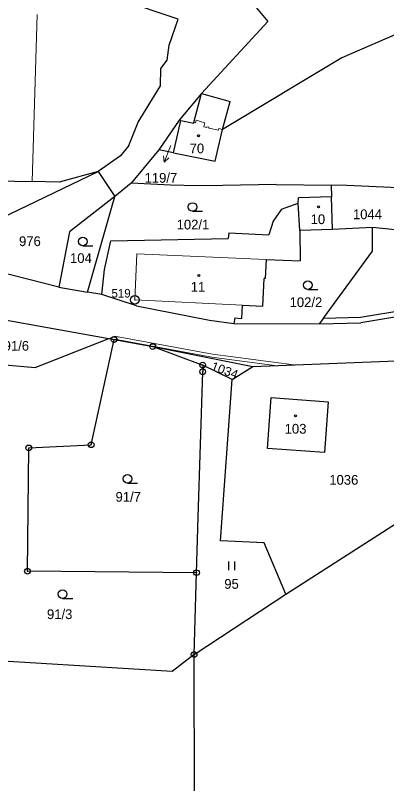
# Model space of a CAD drawing. Extents: x -754970 to -752637, y -970569 to -968179.
# Drawn here: x -752973.4 to -752908.8, y -969522.6 to -969388.8 of the extents above; entities that cross this region are included whole.
import ezdxf
from ezdxf.enums import TextEntityAlignment as Align

# ---------------------------------------------------------------- set-up
doc = ezdxf.new("R2010")
doc.units = 0
doc.header["$LTSCALE"] = 0.68
for name, color, linetype, lineweight in [('1', 7, 'Continuous', 25), ('13', 7, 'Continuous', 13), ('3', 7, 'Continuous', 25), ('4', 7, 'Continuous', 13), ('5', 7, 'Continuous', 25), ('7', 7, 'Continuous', 13), ('8', 7, 'Continuous', 25)]:
    doc.layers.add(name, color=color, linetype=linetype, lineweight=lineweight)
doc.layers.add('2', color=7, linetype='Continuous')

msp = doc.modelspace()

# ---------------------------------------------------------------- linework, layer by layer
at = {"layer": '1'}
for p, q in [((-752945.09, -969389.41), (-752955.13, -969385.98)), ((-752932.64, -969385.92), (-752929.45, -969389.84)), ((-752897.67, -969387.98), (-752916.6, -969396.15)), ((-752946.63, -969393.96), (-752945.09, -969389.41)), ((-752929.45, -969389.84), (-752941, -969402.41)), ((-752946.99, -969396.6), (-752946.63, -969393.96)), ((-752916.6, -969396.15), (-752937.36, -969408.65)), ((-752948.11, -969398.03), (-752946.99, -969396.6)), ((-752948.16, -969401.07), (-752948.11, -969398.03)), ((-752952.03, -969407.36), (-752948.16, -969401.07)), ((-752941, -969402.41), (-752944.89, -969407.01)), ((-752942.33, -969407.44), (-752941, -969402.41)), ((-752941, -969402.41), (-752936.03, -969403.78)), ((-752937.36, -969408.65), (-752936.03, -969403.78)), ((-752944.89, -969407.01), (-752948.44, -969412.22)), ((-752945.87, -969412.71), (-752944.59, -969407.08)), ((-752944.59, -969407.08), (-752942.34, -969407.53)), ((-752953.66, -969411.44), (-752952.03, -969407.36)), ((-752942.34, -969407.53), (-752942.33, -969407.44)), ((-752938.63, -969414.19), (-752937.36, -969408.65)), ((-752953.66, -969411.44), (-752955.11, -969413.24)), ((-752948.44, -969412.22), (-752953.24, -969418)), ((-752945.87, -969412.71), (-752948.44, -969412.22)), ((-752955.11, -969413.24), (-752959, -969415.96)), ((-752945.87, -969412.71), (-752938.63, -969414.19)), ((-752975.99, -969424.16), (-752959, -969415.96)), ((-752959, -969415.96), (-752965.77, -969417.81)), ((-752959, -969415.96), (-752956.07, -969420.31)), ((-752980.48, -969417.53), (-752970.51, -969417.7)), ((-752965.77, -969417.81), (-752970.51, -969417.7)), ((-752953.24, -969418), (-752956.07, -969420.31)), ((-752946.39, -969418.37), (-752953.24, -969418)), ((-752941.73, -969418.49), (-752946.39, -969418.37)), ((-752937.29, -969418.44), (-752941.73, -969418.49)), ((-752928, -969418.24), (-752937.29, -969418.44)), ((-752928, -969418.24), (-752918.45, -969418.33)), ((-752915.73, -969418.39), (-752918.45, -969418.33)), ((-752918.45, -969418.33), (-752918.38, -969420.4)), ((-752906.77, -969418.85), (-752915.73, -969418.39)), ((-752956.07, -969420.31), (-752964.01, -969426.49)), ((-752960.85, -969436.99), (-752956.07, -969420.31)), ((-752918.38, -969420.4), (-752924.13, -969420.58)), ((-752918.18, -969426.06), (-752918.38, -969420.4)), ((-752927.05, -969422.52), (-752924.18, -969421.51)), ((-752924.18, -969421.51), (-752924.13, -969420.58)), ((-752923.9, -969426.28), (-752924.18, -969421.51)), ((-752927.05, -969422.52), (-752928.5, -969424.64)), ((-752928.5, -969424.64), (-752929.26, -969427.01)), ((-752911.21, -969425.74), (-752918.18, -969426.06)), ((-752911.24, -969429.86), (-752911.21, -969425.74)), ((-752907.26, -969426.14), (-752911.21, -969425.74)), ((-752964.01, -969426.49), (-752965.87, -969436.11)), ((-752936.25, -969426.69), (-752936.34, -969427.66)), ((-752936.25, -969426.69), (-752929.26, -969427.01)), ((-752918.18, -969426.06), (-752923.9, -969426.28)), ((-752923.9, -969426.28), (-752923.82, -969431.55)), ((-752957.89, -969433.05), (-752956.78, -969428.07)), ((-752956.78, -969428.07), (-752936.34, -969427.66)), ((-752919.78, -969441.51), (-752911.24, -969429.86)), ((-752929.76, -969431.29), (-752929.93, -969434.61)), ((-752929.76, -969431.29), (-752923.82, -969431.55)), ((-752965.87, -969436.11), (-752979.9, -969432.57)), ((-752958.35, -969437.39), (-752957.89, -969433.05)), ((-752930.3, -969439.43), (-752930.1, -969434.6)), ((-752929.93, -969434.61), (-752930.1, -969434.6)), ((-752965.87, -969436.11), (-752960.85, -969436.99)), ((-752958.35, -969437.39), (-752960.85, -969436.99)), ((-752952.32, -969439.41), (-752958.35, -969437.39)), ((-752913.32, -969441.36), (-752892.34, -969437.83)), ((-752892.24, -969438.82), (-752913.29, -969442.36)), ((-752952.32, -969439.41), (-752939.63, -969441.9)), ((-752933.97, -969441.6), (-752933.85, -969439.26)), ((-752933.85, -969439.26), (-752930.3, -969439.43)), ((-752979.72, -969441.05), (-752957.16, -969445.1)), ((-752935.19, -969441.5), (-752935.36, -969442.49)), ((-752935.19, -969441.5), (-752933.97, -969441.6)), ((-752919.78, -969441.51), (-752920.52, -969442.52)), ((-752919.78, -969441.51), (-752913.32, -969441.36)), ((-752939.63, -969441.9), (-752935.36, -969442.49)), ((-752935.36, -969442.49), (-752920.52, -969442.52)), ((-752920.52, -969442.52), (-752913.29, -969442.36)), ((-752969.96, -969450.14), (-752957.16, -969445.1)), ((-752960.22, -969463.59), (-752956.23, -969445.27)), ((-752949.49, -969446.48), (-752932.04, -969449.98)), ((-752980.96, -969449.2), (-752969.96, -969450.14)), ((-752940.8, -969449.7), (-752940.8, -969450.86)), ((-752935.66, -969452.23), (-752940.8, -969449.7)), ((-752932.04, -969449.98), (-752903.95, -969448.82)), ((-752941.6, -969476.23), (-752940.8, -969450.86)), ((-752935.66, -969452.23), (-752932.04, -969449.98)), ((-752937.68, -969480.36), (-752935.66, -969452.23)), ((-752929.5, -969464.23), (-752928.85, -969455.35)), ((-752928.85, -969455.35), (-752918.98, -969456.12)), ((-752918.98, -969456.12), (-752919.6, -969464.95)), ((-752971.09, -969464.14), (-752960.22, -969463.59)), ((-752919.6, -969464.95), (-752929.5, -969464.23)), ((-752926.34, -969489.6), (-752902.85, -969474.55)), ((-752941.88, -969485.88), (-752941.6, -969476.23)), ((-752930.1, -969480.7), (-752937.68, -969480.36)), ((-752926.34, -969489.6), (-752930.1, -969480.7)), ((-752942.29, -969500.15), (-752941.88, -969485.88)), ((-752942.29, -969500.15), (-752926.34, -969489.6)), ((-752946.12, -969503.08), (-752988.75, -969500.54)), ((-752942.29, -969500.15), (-752946.12, -969503.08)), ((-752942.19, -969568.99), (-752942.29, -969500.15))]:
    msp.add_line(p, q, dxfattribs=at)
for points in [[(-752957.16, -969445.1), (-752956.23, -969445.27), (-752949.49, -969446.48), (-752940.8, -969449.7)], [(-752941.88, -969485.88), (-752971.3, -969485.62), (-752971.09, -969464.14)]]:
    msp.add_lwpolyline(points, dxfattribs=at)
at = {"layer": '13'}
msp.add_lwpolyline([(-752957.12, -969445.11), (-752956.25, -969445.26), (-752956.1, -969445.2), (-752939.19, -969448.3), (-752927.85, -969449.81), (-752924.95, -969449.69), (-752939.11, -969447.81), (-752956.17, -969444.68)], close=True, dxfattribs=at)
at = {"layer": '3'}
for p, q in [((-752942.593, -969422.91), (-752940.843, -969422.91)), ((-752961.683, -969428.94), (-752959.933, -969428.94)), ((-752922.483, -969436.55), (-752920.733, -969436.55)), ((-752953.883, -969470.3), (-752952.133, -969470.3)), ((-752936.221, -969485.42), (-752936.221, -969483.92)), ((-752935.22, -969485.42), (-752935.22, -969483.92)), ((-752965.183, -969490.36), (-752963.433, -969490.36))]:
    msp.add_line(p, q, dxfattribs=at)
for centre in [(-752942.5929, -969422.1598), (-752961.6829, -969428.1898), (-752922.4829, -969435.7998), (-752953.8829, -969469.5498), (-752965.1829, -969489.6098)]:
    msp.add_circle(centre, 0.75, dxfattribs=at)
at = {"layer": '4'}
for p, q in [((-752969.62, -969388.61), (-752970.51, -969417.7)), ((-752940.62, -969408.22), (-752940.15, -969408.32)), ((-752952.6, -969438.35), (-752952.24, -969430.31)), ((-752929.76, -969431.29), (-752952.24, -969430.31)), ((-752952.6, -969438.35), (-752933.85, -969439.26))]:
    msp.add_line(p, q, dxfattribs=at)
for points in [[(-752942.33, -969407.44), (-752942.05, -969407.49), (-752941.91, -969407.04), (-752940.45, -969407.48), (-752940.62, -969408.22)], [(-752940.15, -969408.32), (-752940.1, -969408.18), (-752939.7, -969408.27), (-752939.73, -969408.42)], [(-752939.73, -969408.42), (-752938.02, -969408.8), (-752937.96, -969408.51), (-752937.36, -969408.65)]]:
    msp.add_lwpolyline(points, dxfattribs=at)
at = {"layer": '5'}
for centre in [(-752941.5468, -969409.7392), (-752920.6468, -969422.1492), (-752941.4868, -969434.0892), (-752924.6368, -969458.5492)]:
    msp.add_circle(centre, 0.175, dxfattribs=at)
at = {"layer": '7'}
msp.add_line((-752947.524, -969414.362), (-752946.685, -969413.622), dxfattribs=at)
msp.add_lwpolyline([(-752946.36, -969411.47), (-752946.4, -969411.58), (-752947.524, -969414.362), (-752947.613, -969413.246)], dxfattribs=at)
at = {"layer": '8'}
for centre, radius in [((-752952.6, -969438.3398), 0.75), ((-752952.6, -969438.3398), 0.03), ((-752956.23, -969445.2699), 0.5), ((-752956.23, -969445.2699), 0.0303), ((-752949.49, -969446.4799), 0.5), ((-752949.49, -969446.4799), 0.0303), ((-752940.8, -969449.6999), 0.5), ((-752940.8, -969449.6999), 0.0303), ((-752940.8, -969450.8599), 0.5), ((-752940.8, -969450.8599), 0.0303), ((-752960.22, -969463.5899), 0.5), ((-752971.09, -969464.1399), 0.5), ((-752971.09, -969464.1399), 0.0303), ((-752960.22, -969463.5899), 0.0303), ((-752971.3, -969485.6199), 0.5), ((-752971.3, -969485.6199), 0.0303), ((-752941.88, -969485.8799), 0.5), ((-752941.88, -969485.8799), 0.0303), ((-752942.29, -969500.1499), 0.5), ((-752942.29, -969500.1499), 0.0303)]:
    msp.add_circle(centre, radius, dxfattribs=at)

# ---------------------------------------------------------------- texts
at = {"layer": '2'}
for s, p in [('70', (-752941.809, -969412.805)), ('1044', (-752912.11, -969424.285)), ('102/1', (-752942.49, -969426.075)), ('10', (-752920.739, -969425.145)), ('976', (-752970.879, -969428.975)), ('104', (-752961.999, -969431.915)), ('11', (-752941.609, -969436.915)), ('102/2', (-752922.82, -969439.605)), ('91/6', (-752973.239, -969447.205)), ('103', (-752924.629, -969461.655)), ('1036', (-752916.23, -969470.555)), ('91/7', (-752953.759, -969473.515)), ('95', (-752935.779, -969488.685)), ('91/3', (-752965.699, -969493.965))]:
    msp.add_text(s, height=1.7, dxfattribs=at).set_placement(p, align=Align.CENTER)
msp.add_text('119/7', height=1.7, dxfattribs=at).set_placement((-752945.23, -969417.935), align=Align.RIGHT)
at = {"layer": '2', "width": 1.05}
msp.add_text('1034', height=1.53, rotation=340, dxfattribs=at).set_placement((-752937.2176, -969451.3275), align=Align.CENTER)
at = {"layer": '8'}
msp.add_text('519', height=1.5, dxfattribs=at).set_placement((-752953.339, -969437.937), align=Align.RIGHT)

doc.saveas('drawing.dxf')
